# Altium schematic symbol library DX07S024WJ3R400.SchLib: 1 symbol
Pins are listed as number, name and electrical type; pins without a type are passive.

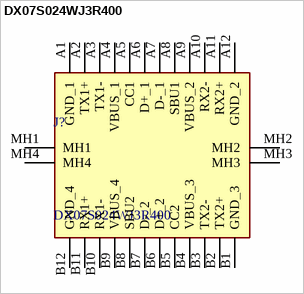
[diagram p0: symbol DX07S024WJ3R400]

## DX07S024WJ3R400
designator J?
Input/Output Connector, USB Type-C connector, 24 pos., Height: 10 mm, 2-row , Vertical-Receptacle; Manufacturer_Name: JAE; Geometry.Height: 10.2mm
footprint DX07S024WJ3R400
pins: A1 GND_1, A2 TX1+, A3 TX1-, A4 VBUS_1, A5 CC1, A6 D+_1, A7 D-_1, A8 SBU1, A9 VBUS_2, A10 RX2-, A11 RX2+, A12 GND_2, B1 GND_3, B2 TX2+, B3 TX2-, B4 VBUS_3, B5 CC2, B6 D+_2, B7 D-_2, B8 SBU2, B9 VBUS_4, B10 RX1-, B11 RX1+, B12 GND_4, MH1, MH2, MH3, MH4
